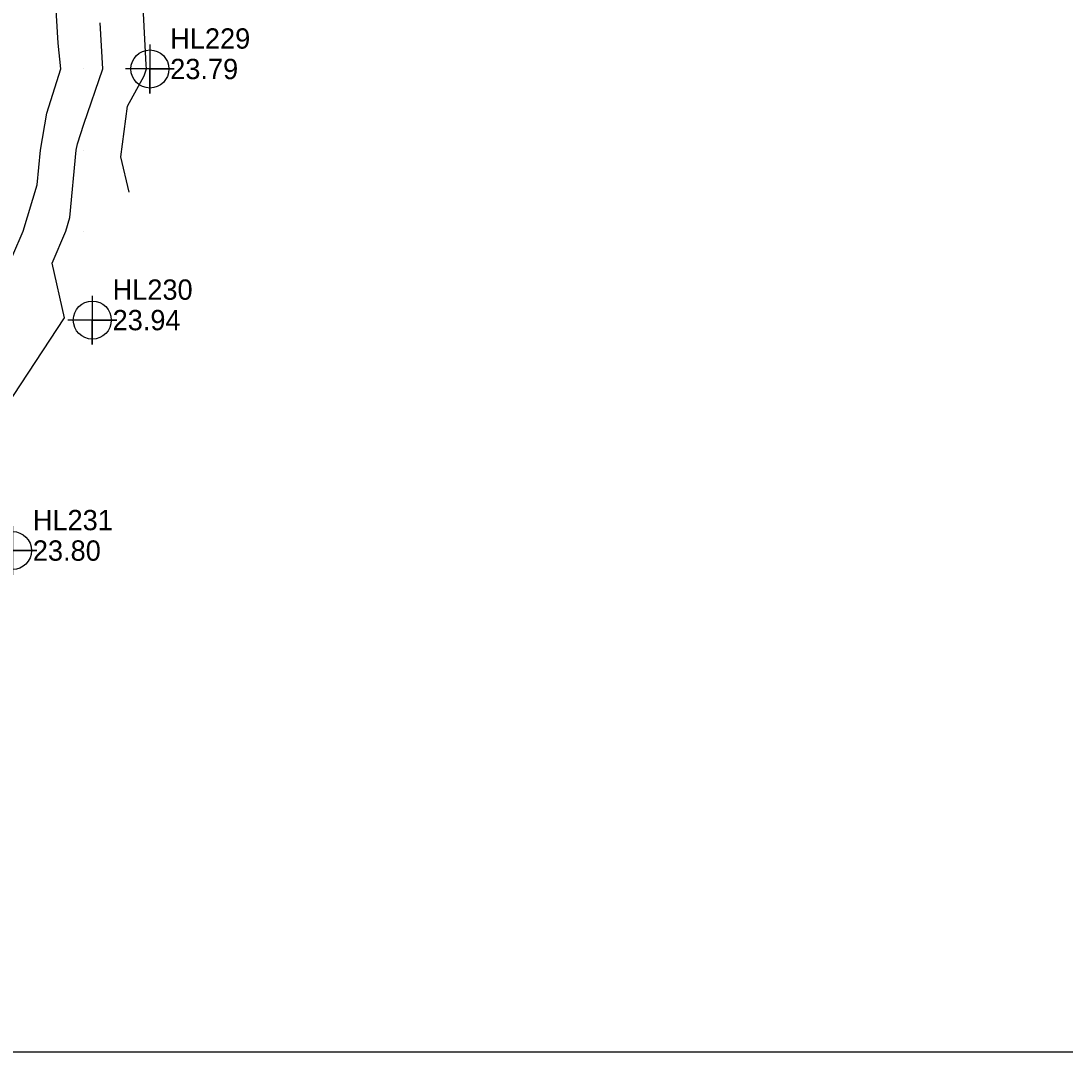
# Model space of a CAD drawing. Extents: x 2531902 to 2533249, y 715219 to 716099.
# Drawn here: x 2532832.3 to 2532960.8, y 715219 to 715345.9 of the extents above; entities that cross this region are included whole.
import ezdxf

# ---------------------------------------------------------------- set-up
doc = ezdxf.new("R2010")
doc.units = 0
for name, color, linetype in [('DTM Contours Major', 7, 'Continuous'), ('DTM Contours Minor', 7, 'Continuous'), ('Exist DTM QL2 LIDAR Elevation Point', 7, 'Continuous'), ('Exist DTM Regular Point CELL', 7, 'Continuous'), ('Exist DTM Regular Point Cogo Elevation', 7, 'Continuous'), ('Exist DTM Regular Point Cogo Number', 7, 'Continuous'), ('Sheet PDF Layout', 7, 'Continuous')]:
    doc.layers.add(name, color=color, linetype=linetype)

msp = doc.modelspace()

# ---------------------------------------------------------------- linework, layer by layer
at = {"layer": 'DTM Contours Major'}
msp.add_lwpolyline([(2532818.71, 715250.69), (2532821.42, 715272.52), (2532825.6, 715283.11), (2532830.49, 715298.51), (2532837.64, 715309.36), (2532836.1, 715316.1), (2532837.79, 715320), (2532838.31, 715321.69), (2532839.09, 715330), (2532839.22, 715330.78), (2532840, 715333.2), (2532842.36, 715339.99), (2532842.03, 715345.64)], dxfattribs=at)
at = {"layer": 'DTM Contours Minor'}
for points in [[(2532845.6, 715324.8), (2532844.59, 715329.17), (2532845.38, 715335.38), (2532847.44, 715339.11), (2532847.74, 715339.97), (2532847.71, 715340.5), (2532847.2, 715350), (2532846.18, 715353.82), (2532845.03, 715360), (2532844.05, 715365.95), (2532844.2, 715370), (2532843.4, 715373.4), (2532841.29, 715380), (2532840, 715383.03), (2532837.92, 715388.76), (2532836.31, 715390), (2532830, 715396.91)], [(2532830, 715314.11), (2532832.56, 715320), (2532834.29, 715325.71), (2532834.7, 715330), (2532835.45, 715334.55), (2532837.2, 715340), (2532836.84, 715343.16), (2532836.44, 715350), (2532835.31, 715354.69), (2532833.95, 715360), (2532830.51, 715369.49)]]:
    msp.add_lwpolyline(points, dxfattribs=at)
at = {"layer": 'Exist DTM QL2 LIDAR Elevation Point'}
for p, q in [((2532840, 715340), (2532840, 715340)), ((2532850, 715340), (2532850, 715340)), ((2532840, 715330), (2532840, 715330)), ((2532840, 715320), (2532840, 715320))]:
    msp.add_line(p, q, dxfattribs=at)
at = {"layer": 'Exist DTM Regular Point CELL'}
for points in [[(2532848.15, 715342.97), (2532848.15, 715336.97), (2532848.15, 715339.97), (2532851.15, 715339.97), (2532845.15, 715339.97)], [(2532841.06, 715312.08), (2532841.06, 715306.08), (2532841.06, 715309.08), (2532844.06, 715309.08), (2532838.06, 715309.08)], [(2532831.24, 715283.73), (2532831.24, 715277.73), (2532831.24, 715280.73), (2532834.24, 715280.73), (2532828.24, 715280.73)]]:
    msp.add_lwpolyline(points, dxfattribs=at)
for centre in [(2532848.15, 715339.97), (2532841.06, 715309.08), (2532831.24, 715280.73)]:
    msp.add_circle(centre, 2.34, dxfattribs=at)
at = {"layer": 'Sheet PDF Layout'}
msp.add_line((2533248.96, 715219.03), (2531901.76, 715219.03), dxfattribs=at)

# ---------------------------------------------------------------- texts
at = {"layer": 'Exist DTM Regular Point Cogo Elevation'}
for s, p in [('23.79', (2532850.65, 715338.72)), ('23.94', (2532843.56, 715307.83)), ('23.80', (2532833.74, 715279.48))]:
    msp.add_text(s, height=2.5, dxfattribs=at).set_placement(p)
at = {"layer": 'Exist DTM Regular Point Cogo Number'}
for s, p in [('HL229', (2532850.65, 715342.47)), ('HL230', (2532843.56, 715311.58)), ('HL231', (2532833.74, 715283.23))]:
    msp.add_text(s, height=2.5, dxfattribs=at).set_placement(p)

doc.saveas('drawing.dxf')
